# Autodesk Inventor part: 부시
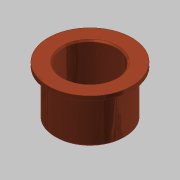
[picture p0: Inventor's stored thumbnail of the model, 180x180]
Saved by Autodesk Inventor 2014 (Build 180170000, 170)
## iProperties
Created: 2015-10
Part Number: 부시
Document SubType Name: Modeling
Designer: mdu
Density: 7.86 g/cm^3
Material: 강철, 연강
Mass: 246.97 g
Surface Area: 129.264 cm^2
Volume: 31.4212 cm^3
Appearance: 구리 - 새틴
Author: mdu
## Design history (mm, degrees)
sketch "스케치1"
  geometry: C1 r 31 at (0, 0) reference; C2 r 25 at (0, 0) reference; C3 r 30 at (0, 0) reference; 1 further point
  node "참조1"
  node "참조2"
  node "참조4"
extrude "돌출1" new body sketch "스케치1" distance "d0" = 3; taper "d1" = 0 deg
extrude "돌출2" join sketch "스케치1" distance "d2" = 35; taper "d3" = 0 deg
chamfer "모따기1" distance "d6" = 1; stored, may be unused: second distance "d7" = 2, angle "d8" = 45 deg
sketch "스케치3"
  geometry: C1 r 19 at (0, 0); 1 further point
  constraints: 1 centre point, 1 coincident
  dimensions: "d13" = 38 diameter of C1
extrude "돌출4" cut sketch "스케치3" stored distance "d14" = 10; taper "d15" = 0 deg
chamfer "모따기3" distance "d16" = 1; stored, may be unused: second distance "d17" = 2, angle "d18" = 45 deg
node "솔리드1"
